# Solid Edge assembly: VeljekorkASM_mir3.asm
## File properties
Author: KULL
Template: Iso Metric Assembly.asm
Last saved by: KULL
Revision: 2
Application: Solid Edge
Username: KULL
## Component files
rehvikork_mir3.par
rehvikork_logo_mir3.par
VeljekorkASM.asm
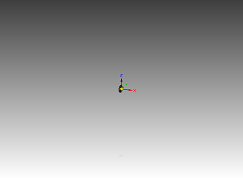
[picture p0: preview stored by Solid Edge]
